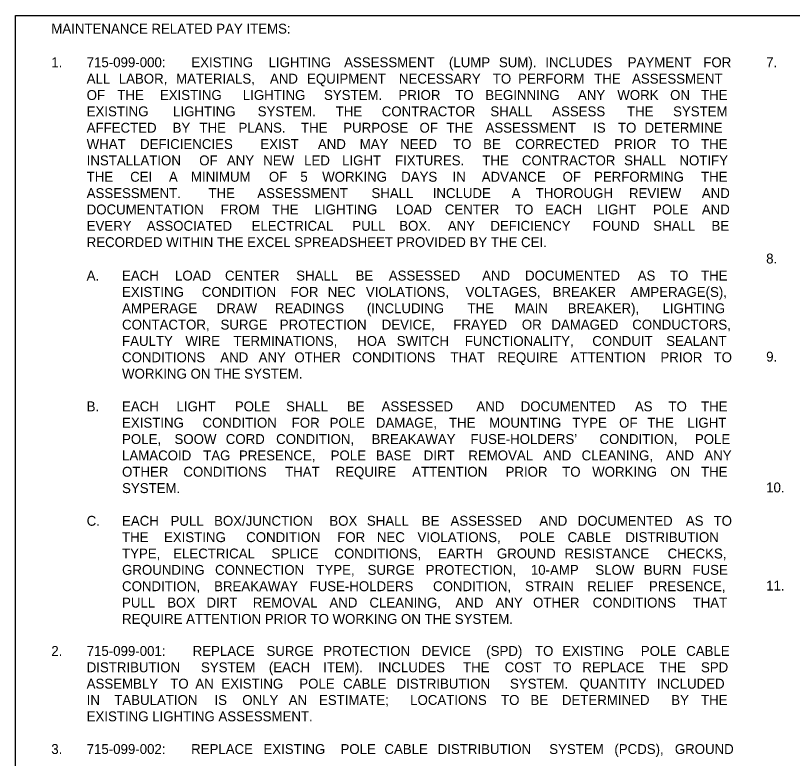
# Model space of a CAD drawing. Extents: x -55 to 2471539, y -90 to 3608906.
# Drawn here: x 0 to 543, y 440 to 960 of the extents above; entities that cross this region are included whole.
import ezdxf

# ---------------------------------------------------------------- set-up
doc = ezdxf.new("R2010")
doc.units = 0
doc.layers.add('NonPlottingEle_dp', color=7, linetype='Continuous')
doc.layers.add('TextNotes', color=7, linetype='Continuous')

msp = doc.modelspace()

# ---------------------------------------------------------------- linework, layer by layer
at = {"layer": 'NonPlottingEle_dp'}
msp.add_lwpolyline([(0, 0), (0, 960), (1540, 960), (1540, 0)], dxfattribs=at)

# ---------------------------------------------------------------- texts
at = {"layer": 'TextNotes'}
for s, p in [('MAINTENANCE RELATED PAY ITEMS:', (25.02, 947.36)), ('1.', (25.02, 923.83)), ('715-099-000: ', (49.75, 923.83)), ('EXISTING ', (122.93, 923.83)), ('LIGHTING ', (176.95, 923.83)), ('ASSESSMENT ', (229.81, 923.83)), ('(LUMP ', (303.12, 923.83)), ('SUM). ', (338.06, 923.83)), ('INCLUDES ', (370.51, 923.83)), ('PAYMENT ', (428.15, 923.83)), ('FOR ', (481.03, 923.83)), ('7.', (524.97, 923.83)), ('ALL ', (49.75, 912.39)), ('LABOR, ', (72.19, 912.39)), ('MATERIALS, ', (112.29, 912.39)), ('AND ', (177.94, 912.39)), ('EQUIPMENT ', (203.87, 912.39)), ('NECESSARY ', (268.15, 912.39)), ('TO ', (333.79, 912.39)), ('PERFORM ', (351.51, 912.39)), ('THE ', (404.7, 912.39)), ('ASSESSMENT ', (431.16, 912.39)), ('OF ', (49.75, 900.96)), ('THE ', (71.16, 900.96)), ('EXISTING ', (100.98, 900.96)), ('LIGHTING ', (158.95, 900.96)), ('SYSTEM. ', (215.73, 900.96)), ('PRIOR ', (267.82, 900.96)), ('TO ', (307.48, 900.96)), ('BEGINNING ', (328.55, 900.96)), ('ANY ', (393.34, 900.96)), ('WORK ', (420.89, 900.96)), ('ON ', (457.81, 900.96)), ('THE ', (479.44, 900.96)), ('EXISTING ', (49.75, 889.52)), ('LIGHTING ', (110.15, 889.52)), ('SYSTEM. ', (169.36, 889.52)), ('CONTRACTOR ', (256.14, 889.52)), ('SHALL ', (332.08, 889.52)), ('ASSESS ', (375.3, 889.52)), ('SYSTEM ', (459.88, 889.52)), ('THE ', (223.89, 889.52)), ('THE ', (427.64, 889.52)), ('AFFECTED ', (49.75, 878.09)), ('BY ', (109.86, 878.09)), ('THE ', (128.65, 878.09)), ('PLANS. ', (155.93, 878.09)), (' THE ', (197.09, 878.09)), ('PURPOSE ', (229.22, 878.09)), ('OF ', (282.55, 878.09)), ('THE ', (301.42, 878.09)), ('ASSESSMENT ', (328.69, 878.09)), ('IS ', (403.95, 878.09)), ('TO ', (421.35, 878.09)), ('DETERMINE ', (439.88, 878.09)), ('WHAT ', (49.75, 866.65)), ('DEFICIENCIES ', (87.07, 866.65)), ('EXIST ', (171.25, 866.65)), ('AND ', (211.47, 866.65)), ('MAY ', (240.69, 866.65)), ('NEED ', (268.96, 866.65)), ('TO ', (305.97, 866.65)), ('BE ', (326.99, 866.65)), ('CORRECTED ', (349.46, 866.65)), ('PRIOR ', (418.82, 866.65)), ('TO ', (458.42, 866.65)), ('THE ', (479.44, 866.65)), ('INSTALLATION ', (49.75, 855.22)), ('OF ', (128.46, 855.22)), ('ANY ', (147.79, 855.22)), ('NEW ', (173.26, 855.22)), ('LED ', (201.84, 855.22)), ('LIGHT ', (228.39, 855.22)), ('FIXTURES. ', (265.39, 855.22)), ('THE ', (326.41, 855.22)), ('CONTRACTOR ', (354.15, 855.22)), ('SHALL ', (425.59, 855.22)), ('NOTIFY ', (464.3, 855.22)), ('THE ', (49.75, 843.78)), ('CEI ', (80.17, 843.78)), ('A ', (107.28, 843.78)), ('MINIMUM ', (122.69, 843.78)), ('OF ', (177.18, 843.78)), ('5 ', (199.19, 843.78)), ('WORKING ', (214.48, 843.78)), ('DAYS ', (269.7, 843.78)), ('IN ', (305.6, 843.78)), ('ADVANCE ', (326.02, 843.78)), ('OF ', (382.58, 843.78)), ('PERFORMING ', (404.6, 843.78)), ('THE ', (479.44, 843.78)), ('ASSESSMENT. ', (49.75, 832.35)), (' THE ', (132.33, 832.35)), ('ASSESSMENT ', (169.07, 832.35)), ('SHALL ', (248.92, 832.35)), ('INCLUDE ', (291.76, 832.35)), ('A ', (346.93, 832.35)), ('THOROUGH ', (363.79, 832.35)), ('REVIEW ', (429, 832.35)), ('AND ', (479.97, 832.35)), ('DOCUMENTATION ', (49.75, 820.92)), ('FROM ', (143.48, 820.92)), ('THE ', (179.37, 820.92)), ('LIGHTING ', (209.2, 820.92)), ('LOAD ', (265.99, 820.92)), ('CENTER ', (300.22, 820.92)), ('TO ', (349.3, 820.92)), ('EACH ', (370.38, 820.92)), ('LIGHT ', (406.75, 820.92)), ('POLE ', (445.84, 820.92)), ('AND ', (479.97, 820.92)), ('EVERY ', (49.75, 809.48)), ('ASSOCIATED ', (91.71, 809.48)), ('ELECTRICAL ', (165.09, 809.48)), ('PULL ', (235.53, 809.48)), ('BOX. ', (268.34, 809.48)), (' ANY ', (299.73, 809.48)), ('DEFICIENCY ', (332.07, 809.48)), ('FOUND ', (403.54, 809.48)), ('SHALL ', (446.01, 809.48)), ('BE ', (486.73, 809.48)), ('RECORDED WITHIN THE EXCEL SPREADSHEET PROVIDED BY THE CEI. ', (49.75, 798.05)), ('8.', (524.97, 786.61)), ('A.', (49.75, 774.7)), ('EACH ', (74.5, 774.7)), ('LOAD ', (111.57, 774.7)), ('CENTER ', (146.5, 774.7)), ('SHALL ', (196.29, 774.7)), ('BE ', (237.79, 774.7)), ('ASSESSED ', (261.03, 774.7)), ('AND ', (326.33, 774.7)), ('DOCUMENTED ', (356.33, 774.7)), ('AS ', (435.12, 774.7)), ('TO ', (457.65, 774.7)), ('THE ', (479.44, 774.7)), ('EXISTING ', (74.5, 763.27)), ('CONDITION ', (130.29, 763.27)), ('FOR ', (192.29, 763.27)), ('NEC ', (218.32, 763.27)), ('VIOLATIONS, ', (245.02, 763.27)), ('VOLTAGES, ', (314.69, 763.27)), ('BREAKER ', (375.63, 763.27)), ('AMPERAGE(S), ', (430.08, 763.27)), ('AMPERAGE ', (74.5, 751.84)), ('DRAW ', (140.66, 751.84)), ('READINGS ', (181.43, 751.84)), ('(INCLUDING ', (245.7, 751.84)), ('THE ', (316.04, 751.84)), ('MAIN ', (349.13, 751.84)), ('BREAKER), ', (386.21, 751.84)), ('LIGHTING ', (452.48, 751.84)), ('CONTACTOR, ', (74.5, 740.4)), ('SURGE ', (143.35, 740.4)), ('PROTECTION ', (184.78, 740.4)), ('DEVICE, ', (256.09, 740.4)), ('FRAYED ', (306.17, 740.4)), ('OR ', (354.09, 740.4)), ('DAMAGED ', (374.76, 740.4)), ('CONDUCTORS, ', (431.31, 740.4)), ('FAULTY ', (74.5, 728.97)), ('WIRE ', (118.81, 728.97)), ('TERMINATIONS, ', (152.44, 728.97)), ('HOA ', (238.98, 728.97)), ('SWITCH ', (266.62, 728.97)), ('FUNCTIONALITY, ', (314.18, 728.97)), ('CONDUIT ', (403.34, 728.97)), ('SEALANT ', (455.05, 728.97)), ('CONDITIONS ', (74.5, 717.53)), ('AND ', (143.2, 717.53)), ('ANY ', (169.98, 717.53)), ('OTHER ', (195.02, 717.53)), ('CONDITIONS ', (235.45, 717.53)), ('THAT ', (304.15, 717.53)), ('REQUIRE ', (337.07, 717.53)), ('ATTENTION ', (388.19, 717.53)), ('PRIOR ', (451.02, 717.53)), ('TO ', (488.18, 717.53)), ('9.', (524.97, 718.01)), ('WORKING ON THE SYSTEM.', (74.5, 706.1)), ('B.', (49.75, 683.23)), ('EACH ', (74.5, 683.23)), ('LIGHT ', (112.58, 683.23)), ('POLE ', (153.38, 683.23)), ('SHALL ', (189.22, 683.23)), ('BE ', (231.74, 683.23)), ('ASSESSED ', (255.99, 683.23)), ('AND ', (322.29, 683.23)), ('DOCUMENTED ', (353.3, 683.23)), ('AS ', (433.1, 683.23)), ('TO ', (456.64, 683.23)), ('THE ', (479.44, 683.23)), ('EXISTING ', (74.5, 671.79)), ('CONDITION ', (130.73, 671.79)), ('FOR ', (193.17, 671.79)), ('POLE ', (219.65, 671.79)), ('DAMAGE, ', (252.02, 671.79)), ('THE ', (303.13, 671.79)), ('MOUNTING ', (331.2, 671.79)), ('TYPE ', (389.38, 671.79)), ('OF ', (422.14, 671.79)), ('THE ', (441.8, 671.79)), ('LIGHT ', (469.88, 671.79)), ('POLE, ', (74.5, 660.36)), ('SOOW ', (111.17, 660.36)), ('CORD ', (147.04, 660.36)), ('CONDITION, ', (182.24, 660.36)), ('BREAKAWAY ', (248.99, 660.36)), ('FUSE-HOLDERS’ ', (318.13, 660.36)), ('CONDITION, ', (408.4, 660.36)), ('POLE ', (475.14, 660.36)), ('LAMACOID ', (74.5, 648.92)), ('TAG ', (131.23, 648.92)), ('PRESENCE, ', (156.22, 648.92)), ('POLE ', (220.4, 648.92)), ('BASE ', (252.05, 648.92)), ('DIRT ', (285.47, 648.92)), ('REMOVAL ', (316.67, 648.92)), ('AND ', (369.09, 648.92)), ('CLEANING, ', (395.9, 648.92)), ('AND ', (454.89, 648.92)), ('ANY ', (481.71, 648.92)), ('OTHER ', (74.5, 637.49)), ('CONDITIONS ', (117.37, 637.49)), ('THAT ', (188.51, 637.49)), ('REQUIRE ', (223.87, 637.49)), ('ATTENTION ', (277.43, 637.49)), ('PRIOR ', (342.7, 637.49)), ('TO ', (382.3, 637.49)), ('WORKING ', (403.31, 637.49)), ('ON ', (457.87, 637.49)), ('THE ', (479.44, 637.49)), ('SYSTEM.', (74.5, 626.06)), ('10.', (524.97, 626.53)), ('C.', (49.75, 603.19)), ('EACH ', (74.5, 603.19)), ('PULL ', (108.42, 603.19)), ('BOX/JUNCTION ', (138.86, 603.19)), ('BOX ', (219.46, 603.19)), ('SHALL ', (245.74, 603.19)), ('BE ', (284.09, 603.19)), ('ASSESSED ', (304.18, 603.19)), ('AND ', (366.32, 603.19)), ('DOCUMENTED ', (393.17, 603.19)), ('AS ', (468.8, 603.19)), ('TO ', (488.18, 603.19)), ('THE ', (74.5, 591.75)), ('EXISTING ', (103.83, 591.75)), ('CONDITION ', (161.31, 591.75)), ('FOR ', (225, 591.75)), ('NEC ', (252.73, 591.75)), ('VIOLATIONS, ', (281.12, 591.75)), ('POLE ', (352.48, 591.75)), ('CABLE ', (386.11, 591.75)), ('DISTRIBUTION ', (426.48, 591.75)), ('TYPE, ', (74.5, 580.32)), ('ELECTRICAL ', (110.25, 580.32)), ('SPLICE ', (178.98, 580.32)), ('CONDITIONS, ', (222.99, 580.32)), ('EARTH ', (295.44, 580.32)), ('GROUND ', (336.64, 580.32)), ('RESISTANCE ', (383.89, 580.32)), ('CHECKS, ', (456.02, 580.32)), ('GROUNDING ', (74.5, 568.88)), ('CONNECTION ', (139.54, 568.88)), ('TYPE, ', (210.37, 568.88)), ('SURGE ', (246.21, 568.88)), ('PROTECTION, ', (286.84, 568.88)), ('10-AMP ', (360.39, 568.88)), ('SLOW ', (405.51, 568.88)), ('BURN ', (439.35, 568.88)), ('FUSE ', (473.44, 568.88)), ('CONDITION, ', (74.5, 557.45)), ('BREAKAWAY ', (138.87, 557.45)), ('FUSE-HOLDERS ', (205.64, 557.45)), ('CONDITION, ', (292, 557.45)), ('STRAIN ', (356.38, 557.45)), ('RELIEF ', (399.82, 557.45)), ('PRESENCE, ', (442.99, 557.45)), ('11.', (524.97, 557.92)), ('PULL ', (74.5, 546.01)), ('BOX ', (106.1, 546.01)), ('DIRT ', (133.54, 546.01)), ('REMOVAL ', (165.92, 546.01)), ('AND ', (219.53, 546.01)), ('CLEANING, ', (247.53, 546.01)), ('AND ', (307.7, 546.01)), ('ANY ', (335.71, 546.01)), ('OTHER ', (361.97, 546.01)), ('CONDITIONS ', (403.62, 546.01)), ('THAT ', (473.54, 546.01)), ('REQUIRE ATTENTION PRIOR TO WORKING ON THE SYSTEM.', (74.5, 534.58)), ('2.', (25.02, 512.18)), ('715-099-001: ', (49.75, 512.18)), ('REPLACE ', (123.87, 512.18)), ('SURGE ', (175.48, 512.18)), ('PROTECTION ', (215.21, 512.18)), ('DEVICE ', (284.01, 512.18)), ('(SPD) ', (329.21, 512.18)), ('TO ', (363.3, 512.18)), ('EXISTING ', (382.35, 512.18)), ('POLE ', (437.31, 512.18)), ('CABLE ', (469.06, 512.18)), ('DISTRIBUTION ', (49.75, 500.75)), ('SYSTEM ', (129.71, 500.75)), ('(EACH ', (177.17, 500.75)), ('ITEM). ', (215.19, 500.75)), ('INCLUDES ', (253.54, 500.75)), ('THE ', (312.98, 500.75)), ('COST ', (342.12, 500.75)), ('TO ', (376.01, 500.75)), ('REPLACE ', (396.4, 500.75)), ('THE ', (450.25, 500.75)), ('SPD ', (479.38, 500.75)), ('ASSEMBLY ', (49.75, 489.32)), ('TO ', (108.18, 489.32)), ('AN ', (125.77, 489.32)), ('EXISTING ', (143.97, 489.32)), ('POLE ', (198.47, 489.32)), ('CABLE ', (229.1, 489.32)), ('DISTRIBUTION ', (266.49, 489.32)), ('SYSTEM. ', (345.79, 489.32)), ('QUANTITY ', (394.41, 489.32)), ('INCLUDED ', (448.53, 489.32)), ('IN ', (49.75, 477.88)), ('TABULATION ', (69.05, 477.88)), ('IS ', (139.12, 477.88)), ('ONLY ', (158.56, 477.88)), ('AN ', (191.04, 477.88)), ('ESTIMATE; ', (212.21, 477.88)), ('LOCATIONS ', (275.99, 477.88)), ('TO ', (339.56, 477.88)), ('BE ', (360.12, 477.88)), ('DETERMINED ', (382.14, 477.88)), ('BY ', (458.61, 477.88)), ('THE ', (479.44, 477.88)), ('EXISTING LIGHTING ASSESSMENT.', (49.75, 466.45)), ('3.', (25.02, 443.58)), ('715-099-002: ', (49.75, 443.58)), ('REPLACE ', (122.81, 443.58)), ('EXISTING ', (173.37, 443.58)), ('POLE ', (227.28, 443.58)), ('CABLE ', (257.97, 443.58)), ('DISTRIBUTION ', (295.23, 443.58)), ('SYSTEM ', (373.27, 443.58)), ('(PCDS), ', (418.81, 443.58)), ('GROUND ', (461.11, 443.58))]:
    msp.add_text(s, height=6.93, dxfattribs=at).set_placement(p)

doc.saveas('drawing.dxf')
